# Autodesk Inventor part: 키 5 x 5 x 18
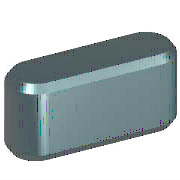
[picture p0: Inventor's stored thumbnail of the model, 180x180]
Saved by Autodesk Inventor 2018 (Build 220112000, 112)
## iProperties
Created: 2012-02
Part Number: 키 5 x 5 x 18
Material: 강철, 연강
Description: 키 및 해당 키홈
Document SubType Name: Modeling
Standard: KS B 1311
Designer: P15F
Standards Organization: KS
Language: ko-KR
Size Designation: 5 x 5 x 18
Categories: <MemberInstance><Categories><Category DisplayName="샤프트 부품" InternalName="7f7aeb1f-a693-4053-b835-cee3144e0d98" Mnemonic="SHFT"><Category DisplayName="키" Interna
Density: 1 g/cm^3
Appearance: 노란색
IsCustomPart: 1
Author: P15F
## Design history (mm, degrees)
workplane "Work Plane1"
workplane "Work Plane2"
sketch "스케치1"
  geometry: L1 (2.5, 2.5)-(15.5, 2.5); L2 (15.5, -2.5)-(2.5, -2.5); L3 (0, 9.4)-(0, -7.4) reference; L4 (-5, 0)-(30, 0) reference; L5 (18, 0)-(18, 7); A1 r 2.5 centre (2.5, 0) between (2.5, 2.5) and (2.5, -2.5); A2 r 2.5 centre (15.5, 0) between (15.5, -2.5) and (15.5, 2.5)
  constraints: 6 end point, 5 point on circle, 4 tangent, 3 point on line, 2 centre point, 1 horizontal, 1 parallel, 1 perpendicular
  dimensions: "d0" = 2.5 radius of A1 (= 0.5 x PB); "d13" = 2.5 radius of A2 (= 0.5 x PB); "d14" = 18 distance between parallel lines of L5 L3 (= NLG)
extrude "본체1" new body sketch "스케치1" taper "d3" = 0 deg; stored distance "d4" = 10
workplane "Work Plane3"
body "Solid1"
chamfer "모따기1" distance "d8" = 0.4 (= PHH); stored, may be unused: second distance "d9" = 0.4 (= PHH), angle "d15" = 45 deg
other parameters: "d1" = -3 (= -PNT), "d2" = 2 (= PH - PNT), "NLG" = 18 [user parameter; used in 3 equation terms], "PB" = 5 [user parameter; used in 2 equation terms], "PNT" = 3 [user parameter; used in 2 equation terms], "PH" = 5 [user parameter; used in 1 equation term], "PHH" = 0.4 [user parameter; used in 2 equation terms], "d10" = 0, "d16" = 0, "d17" = 0, "d18" = 0, "WDMIN" = 12 [user parameter], "PLB2" = 18 (= NLG) [user parameter], "WDMAX" = 17 [user parameter], "PLB1" = 18 (= NLG) [user parameter], "RR" = 0.16 [user parameter], "PUEB" = 2.3 [user parameter]
